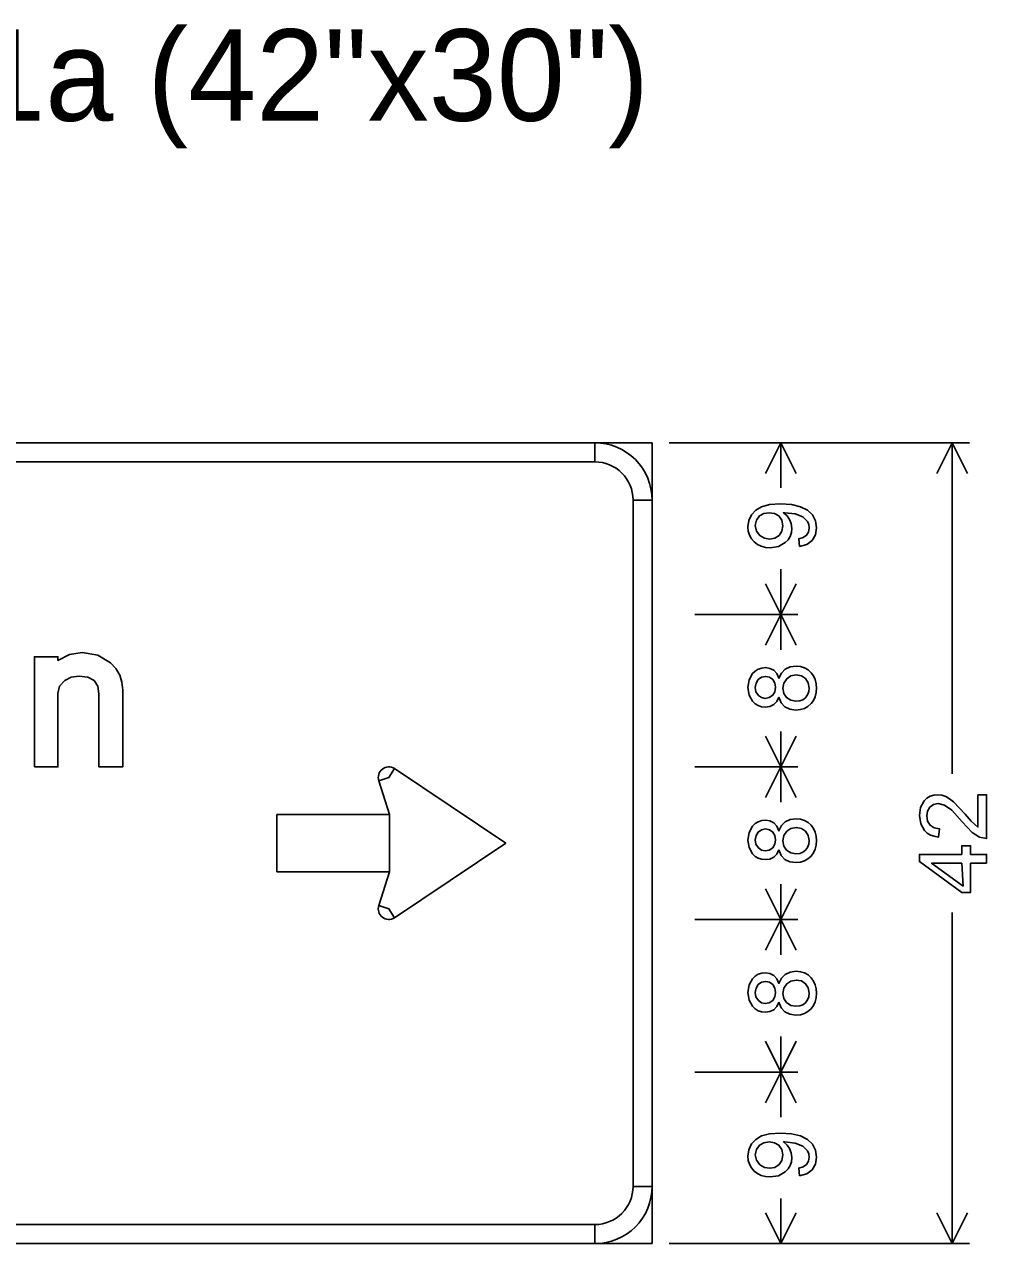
# Model space of a CAD drawing. Extents: x 620864 to 620948.6, y 415499.7 to 415559.1.
# Drawn here: x 620910.82 to 620915.03, y 415523.96 to 415529.29 of the extents above; entities that cross this region are included whole.
import ezdxf

# ---------------------------------------------------------------- set-up
doc = ezdxf.new("R2010")
doc.units = 0
doc.layers.add('SIGNS', color=7, linetype='Continuous')

msp = doc.modelspace()

# ---------------------------------------------------------------- linework, layer by layer
at = {"layer": 'SIGNS'}
for p, q in [((620913.568, 415527.462), (620905.568, 415527.462)), ((620913.318, 415527.462), (620913.318, 415527.3787)), ((620913.568, 415523.962), (620913.568, 415527.462)), ((620914.9555, 415527.462), (620913.643, 415527.462)), ((620914.2055, 415527.462), (620913.7555, 415527.462)), ((620914.0634, 415527.3279), (620914.1305, 415527.462)), ((620914.1305, 415527.265), (620914.1305, 415527.462)), ((620914.1976, 415527.3279), (620914.1305, 415527.462)), ((620914.8134, 415527.3279), (620914.8805, 415527.462)), ((620914.8805, 415526.0148), (620914.8805, 415527.462)), ((620914.9476, 415527.3279), (620914.8805, 415527.462)), ((620913.4846, 415527.212), (620913.568, 415527.212)), ((620914.1305, 415526.9091), (620914.1305, 415526.712)), ((620914.0634, 415526.8462), (620914.1305, 415526.712)), ((620914.1976, 415526.8462), (620914.1305, 415526.712)), ((620914.2055, 415526.712), (620913.7555, 415526.712)), ((620914.0634, 415526.5779), (620914.1305, 415526.712)), ((620914.1305, 415526.5574), (620914.1305, 415526.712)), ((620914.1976, 415526.5779), (620914.1305, 415526.712)), ((620914.1305, 415526.2), (620914.1305, 415526.0454)), ((620914.0634, 415526.1795), (620914.1305, 415526.0454)), ((620914.1976, 415526.1795), (620914.1305, 415526.0454)), ((620912.4176, 415525.9985), (620912.4422, 415526.0384)), ((620914.2055, 415526.0454), (620913.7555, 415526.0454)), ((620914.0634, 415525.9112), (620914.1305, 415526.0454)), ((620914.1305, 415525.8907), (620914.1305, 415526.0454)), ((620914.1976, 415525.9112), (620914.1305, 415526.0454)), ((620912.3729, 415525.9844), (620912.4176, 415525.9985)), ((620914.0634, 415525.5129), (620914.1305, 415525.3787)), ((620914.1305, 415525.5334), (620914.1305, 415525.3787)), ((620914.1976, 415525.5129), (620914.1305, 415525.3787)), ((620912.4176, 415525.4255), (620912.3729, 415525.4397)), ((620912.4422, 415525.3857), (620912.4176, 415525.4255)), ((620914.8805, 415525.4093), (620914.8805, 415523.962)), ((620914.2055, 415525.3787), (620913.7555, 415525.3787)), ((620914.0634, 415525.2445), (620914.1305, 415525.3787)), ((620914.1305, 415525.224), (620914.1305, 415525.3787)), ((620914.1976, 415525.2445), (620914.1305, 415525.3787)), ((620914.1305, 415524.8667), (620914.1305, 415524.712)), ((620914.0634, 415524.8462), (620914.1305, 415524.712)), ((620914.1976, 415524.8462), (620914.1305, 415524.712)), ((620914.2055, 415524.712), (620913.7555, 415524.712)), ((620914.2055, 415524.712), (620913.7555, 415524.712)), ((620914.0634, 415524.5779), (620914.1305, 415524.712)), ((620914.1305, 415524.515), (620914.1305, 415524.712)), ((620914.1976, 415524.5779), (620914.1305, 415524.712)), ((620913.568, 415524.212), (620913.4846, 415524.212)), ((620914.1305, 415524.1591), (620914.1305, 415523.962)), ((620914.0634, 415524.0962), (620914.1305, 415523.962)), ((620914.1976, 415524.0962), (620914.1305, 415523.962)), ((620914.8134, 415524.0962), (620914.8805, 415523.962)), ((620914.9476, 415524.0962), (620914.8805, 415523.962)), ((620913.318, 415524.0454), (620913.318, 415523.962)), ((620905.568, 415523.962), (620913.568, 415523.962)), ((620914.9555, 415523.962), (620913.643, 415523.962)), ((620914.2055, 415523.962), (620913.7555, 415523.962))]:
    msp.add_line(p, q, dxfattribs=at)
for points in [[(620913.318, 415527.3787), (620905.818, 415527.3787), (620905.818, 415527.462), (620913.318, 415527.462), (620913.318, 415527.3787), (620913.318, 415527.3787)], [(620913.4846, 415524.212), (620913.4846, 415527.212), (620913.568, 415527.212), (620913.568, 415524.212), (620913.4846, 415524.212), (620913.4846, 415524.212)], [(620910.868, 415526.0454), (620910.9705, 415526.0454), (620910.9705, 415526.3657), (620910.9777, 415526.3985), (620911, 415526.4237), (620911.0284, 415526.4375), (620911.0639, 415526.4422), (620911.1013, 415526.4371), (620911.1284, 415526.4227), (620911.1446, 415526.3987), (620911.15, 415526.365), (620911.15, 415526.0454), (620911.2536, 415526.0454), (620911.2536, 415526.3807), (620911.2501, 415526.4155), (620911.2404, 415526.4471), (620911.2237, 415526.4754), (620911.2009, 415526.5007), (620911.1443, 415526.5341), (620911.0769, 415526.5454), (620911.0212, 415526.5367), (620910.9707, 415526.5109), (620910.9707, 415526.5267), (620910.868, 415526.5267)], [(620912.928, 415525.712), (620912.4422, 415526.0384), (620912.4176, 415525.9985), (620912.3729, 415525.9844), (620912.4194, 415525.837), (620912.4194, 415525.587), (620912.3729, 415525.4397), (620912.4176, 415525.4255), (620912.4422, 415525.3857), (620912.928, 415525.712), (620912.928, 415525.712)], [(620914.9922, 415525.9237), (620914.9922, 415525.7823), (620914.9625, 415525.8082), (620914.9368, 415525.8383), (620914.8861, 415525.893), (620914.8688, 415525.9063), (620914.8515, 415525.916), (620914.8342, 415525.9217), (620914.8169, 415525.9237), (620914.7992, 415525.922), (620914.7835, 415525.9169), (620914.7696, 415525.9084), (620914.7575, 415525.8968), (620914.7421, 415525.8682), (620914.7369, 415525.8332), (620914.7423, 415525.7961), (620914.7583, 415525.7673), (620914.7703, 415525.7562), (620914.7845, 415525.7478), (620914.8012, 415525.7421), (620914.8202, 415525.739), (620914.8239, 415525.7752), (620914.8012, 415525.779), (620914.7837, 415525.7902), (620914.7725, 415525.8079), (620914.7688, 415525.8313), (620914.7724, 415525.8522), (620914.7824, 415525.8693), (620914.7987, 415525.8813), (620914.8191, 415525.8854), (620914.847, 415525.8779), (620914.8778, 415525.8558), (620914.9233, 415525.8057), (620914.9672, 415525.7594), (620914.9996, 415525.7386), (620915.0305, 415525.7322), (620915.0305, 415525.9237)], [(620911.928, 415525.587), (620911.928, 415525.837), (620912.4194, 415525.837), (620912.4194, 415525.587), (620911.928, 415525.587), (620911.928, 415525.587)], [(620905.818, 415524.0454), (620913.318, 415524.0454), (620913.318, 415523.962), (620905.818, 415523.962), (620905.818, 415524.0454), (620905.818, 415524.0454)]]:
    msp.add_lwpolyline(points, close=True, dxfattribs=at)
for points in [[(620914.2125, 415527.0087), (620914.244, 415527.0176), (620914.2674, 415527.0347), (620914.2821, 415527.0592), (620914.2869, 415527.0905), (620914.2826, 415527.1205), (620914.2694, 415527.1465), (620914.2476, 415527.1675), (620914.2169, 415527.1827), (620914.1774, 415527.1917), (620914.129, 415527.1947), (620914.0814, 415527.1917), (620914.0464, 415527.1825), (620914.0217, 415527.1678), (620914.0027, 415527.1475), (620913.9908, 415527.1226), (620913.9869, 415527.0948), (620913.9887, 415527.0759), (620913.9937, 415527.0586), (620914.002, 415527.043), (620914.0136, 415527.0293), (620914.0281, 415527.0178), (620914.0445, 415527.0097), (620914.0633, 415527.0048), (620914.0841, 415527.0032), (620914.1203, 415527.0088), (620914.1503, 415527.0257), (620914.1627, 415527.0385), (620914.1715, 415527.0531), (620914.1768, 415527.0696), (620914.1784, 415527.0879), (620914.1761, 415527.1089), (620914.1692, 415527.1273), (620914.1578, 415527.143), (620914.1419, 415527.1562), (620914.149, 415527.1565), (620914.1929, 415527.1511), (620914.2266, 415527.1379), (620914.2474, 415527.118), (620914.2532, 415527.1047), (620914.255, 415527.0898), (620914.252, 415527.0719), (620914.2434, 415527.0581), (620914.2291, 415527.0482), (620914.2092, 415527.0425), (620914.2125, 415527.0087)], [(620914.08, 415527.1565), (620914.1035, 415527.1528), (620914.1222, 415527.1424), (620914.1357, 415527.124), (620914.1401, 415527.0997), (620914.1359, 415527.0759), (620914.1233, 415527.0572), (620914.1052, 415527.0454), (620914.0828, 415527.0415), (620914.0591, 415527.0454), (620914.0389, 415527.057), (620914.0238, 415527.0763), (620914.0188, 415527.1007), (620914.0238, 415527.1241), (620914.038, 415527.1424), (620914.0572, 415527.1528), (620914.08, 415527.1565)], [(620914.1225, 415526.3502), (620914.1329, 415526.3256), (620914.1488, 415526.308), (620914.1701, 415526.2976), (620914.1969, 415526.2942), (620914.2165, 415526.2959), (620914.2339, 415526.3013), (620914.2495, 415526.3099), (620914.2628, 415526.3221), (620914.2734, 415526.3363), (620914.2808, 415526.3523), (620914.2854, 415526.3702), (620914.2869, 415526.3899), (620914.2855, 415526.4091), (620914.281, 415526.4269), (620914.2735, 415526.4429), (620914.263, 415526.4573), (620914.2498, 415526.4697), (620914.2344, 415526.4787), (620914.2172, 415526.4839), (620914.1979, 415526.4856), (620914.1717, 415526.4822), (620914.1503, 415526.4723), (620914.134, 415526.4558), (620914.1225, 415526.4328), (620914.1128, 415526.4531), (620914.0996, 415526.4676), (620914.0832, 415526.4763), (620914.0637, 415526.4793), (620914.0471, 415526.4776), (620914.0322, 415526.4727), (620914.0189, 415526.4645), (620914.0071, 415526.4532), (620913.992, 415526.4258), (620913.9869, 415526.3926), (620913.9919, 415526.3595), (620914.0067, 415526.3326), (620914.0182, 415526.3213), (620914.0313, 415526.3133), (620914.0461, 415526.3085), (620914.0627, 415526.3069), (620914.0829, 415526.3096), (620914.0996, 415526.3177), (620914.1128, 415526.3312), (620914.1225, 415526.3502)], [(620914.1969, 415526.3325), (620914.1744, 415526.3366), (620914.156, 415526.3485), (620914.144, 415526.3665), (620914.1401, 415526.389), (620914.1444, 415526.412), (620914.1566, 415526.4308), (620914.1752, 415526.4432), (620914.1981, 415526.4474), (620914.2209, 415526.4433), (620914.239, 415526.4312), (620914.251, 415526.4128), (620914.255, 415526.3902), (620914.2531, 415526.3746), (620914.2474, 415526.3604), (620914.2385, 415526.348), (620914.2271, 415526.3393), (620914.2133, 415526.3341), (620914.1969, 415526.3325)], [(620914.0623, 415526.3452), (620914.0462, 415526.3484), (620914.0326, 415526.3579), (620914.0222, 415526.3738), (620914.0188, 415526.3931), (620914.0223, 415526.4119), (620914.0323, 415526.4273), (620914.0469, 415526.4376), (620914.0643, 415526.441), (620914.082, 415526.4374), (620914.096, 415526.4272), (620914.1052, 415526.412), (620914.1081, 415526.3935), (620914.105, 415526.3738), (620914.0952, 415526.3584), (620914.0805, 415526.3484), (620914.0623, 415526.3452)], [(620914.1225, 415525.6836), (620914.1329, 415525.6589), (620914.1488, 415525.6414), (620914.1701, 415525.6309), (620914.1969, 415525.6275), (620914.2165, 415525.6293), (620914.2339, 415525.6346), (620914.2495, 415525.6433), (620914.2628, 415525.6554), (620914.2734, 415525.6696), (620914.2808, 415525.6856), (620914.2854, 415525.7035), (620914.2869, 415525.7233), (620914.2855, 415525.7425), (620914.281, 415525.7602), (620914.2735, 415525.7762), (620914.263, 415525.7907), (620914.2498, 415525.803), (620914.2344, 415525.812), (620914.2172, 415525.8172), (620914.1979, 415525.819), (620914.1717, 415525.8155), (620914.1503, 415525.8056), (620914.134, 415525.7892), (620914.1225, 415525.7661), (620914.1128, 415525.7864), (620914.0996, 415525.8009), (620914.0832, 415525.8096), (620914.0637, 415525.8126), (620914.0471, 415525.8109), (620914.0322, 415525.806), (620914.0189, 415525.7978), (620914.0071, 415525.7866), (620913.992, 415525.7591), (620913.9869, 415525.7259), (620913.9919, 415525.6928), (620914.0067, 415525.6659), (620914.0182, 415525.6546), (620914.0313, 415525.6466), (620914.0461, 415525.6419), (620914.0627, 415525.6403), (620914.0829, 415525.643), (620914.0996, 415525.651), (620914.1128, 415525.6645), (620914.1225, 415525.6836)], [(620914.0623, 415525.6786), (620914.0462, 415525.6818), (620914.0326, 415525.6912), (620914.0222, 415525.7072), (620914.0188, 415525.7264), (620914.0223, 415525.7452), (620914.0323, 415525.7606), (620914.0469, 415525.7709), (620914.0643, 415525.7743), (620914.082, 415525.7707), (620914.096, 415525.7605), (620914.1052, 415525.7453), (620914.1081, 415525.7268), (620914.105, 415525.7072), (620914.0952, 415525.6917), (620914.0805, 415525.6818), (620914.0623, 415525.6786)], [(620914.1969, 415525.6658), (620914.1744, 415525.6699), (620914.156, 415525.6819), (620914.144, 415525.6998), (620914.1401, 415525.7223), (620914.1444, 415525.7454), (620914.1566, 415525.7641), (620914.1752, 415525.7765), (620914.1981, 415525.7807), (620914.2209, 415525.7766), (620914.239, 415525.7645), (620914.251, 415525.7462), (620914.255, 415525.7235), (620914.2531, 415525.708), (620914.2474, 415525.6937), (620914.2385, 415525.6814), (620914.2271, 415525.6727), (620914.2133, 415525.6674), (620914.1969, 415525.6658)], [(620915.0305, 415525.6247), (620915.0305, 415525.663), (620914.9603, 415525.663), (620914.9603, 415525.7008), (620914.922, 415525.7008), (620914.922, 415525.663), (620914.7369, 415525.663), (620914.7369, 415525.6315), (620914.922, 415525.497), (620914.9603, 415525.497), (620914.9603, 415525.6247), (620915.0305, 415525.6247)], [(620914.922, 415525.6247), (620914.9273, 415525.5246), (620914.7895, 415525.6247), (620914.922, 415525.6247)], [(620914.1225, 415525.0169), (620914.1329, 415524.9922), (620914.1488, 415524.9747), (620914.1701, 415524.9642), (620914.1969, 415524.9608), (620914.2165, 415524.9626), (620914.2339, 415524.9679), (620914.2495, 415524.9766), (620914.2628, 415524.9888), (620914.2734, 415525.0029), (620914.2808, 415525.019), (620914.2854, 415525.0368), (620914.2869, 415525.0566), (620914.2855, 415525.0758), (620914.281, 415525.0936), (620914.2735, 415525.1095), (620914.263, 415525.124), (620914.2498, 415525.1364), (620914.2344, 415525.1454), (620914.2172, 415525.1505), (620914.1979, 415525.1523), (620914.1717, 415525.1488), (620914.1503, 415525.1389), (620914.134, 415525.1225), (620914.1225, 415525.0995), (620914.1128, 415525.1197), (620914.0996, 415525.1343), (620914.0832, 415525.1429), (620914.0637, 415525.1459), (620914.0471, 415525.1443), (620914.0322, 415525.1393), (620914.0189, 415525.1312), (620914.0071, 415525.1199), (620913.992, 415525.0925), (620913.9869, 415525.0593), (620913.9919, 415525.0262), (620914.0067, 415524.9992), (620914.0182, 415524.988), (620914.0313, 415524.98), (620914.0461, 415524.9752), (620914.0627, 415524.9736), (620914.0829, 415524.9763), (620914.0996, 415524.9844), (620914.1128, 415524.9978), (620914.1225, 415525.0169)], [(620914.1969, 415524.9991), (620914.1744, 415525.0032), (620914.156, 415525.0152), (620914.144, 415525.0331), (620914.1401, 415525.0557), (620914.1444, 415525.0787), (620914.1566, 415525.0975), (620914.1752, 415525.1098), (620914.1981, 415525.114), (620914.2209, 415525.1099), (620914.239, 415525.0979), (620914.251, 415525.0795), (620914.255, 415525.0569), (620914.2531, 415525.0413), (620914.2474, 415525.0271), (620914.2385, 415525.0147), (620914.2271, 415525.006), (620914.2133, 415525.0007), (620914.1969, 415524.9991)], [(620914.0623, 415525.0119), (620914.0462, 415525.0151), (620914.0326, 415525.0246), (620914.0222, 415525.0405), (620914.0188, 415525.0598), (620914.0223, 415525.0785), (620914.0323, 415525.094), (620914.0469, 415525.1043), (620914.0643, 415525.1076), (620914.082, 415525.104), (620914.096, 415525.0939), (620914.1052, 415525.0786), (620914.1081, 415525.0602), (620914.105, 415525.0405), (620914.0952, 415525.0251), (620914.0805, 415525.0151), (620914.0623, 415525.0119)], [(620914.2125, 415524.2587), (620914.244, 415524.2676), (620914.2674, 415524.2847), (620914.2821, 415524.3092), (620914.2869, 415524.3405), (620914.2826, 415524.3705), (620914.2694, 415524.3965), (620914.2476, 415524.4175), (620914.2169, 415524.4327), (620914.1774, 415524.4417), (620914.129, 415524.4447), (620914.0814, 415524.4417), (620914.0464, 415524.4325), (620914.0217, 415524.4178), (620914.0027, 415524.3975), (620913.9908, 415524.3726), (620913.9869, 415524.3448), (620913.9887, 415524.3259), (620913.9937, 415524.3086), (620914.002, 415524.293), (620914.0136, 415524.2793), (620914.0281, 415524.2678), (620914.0445, 415524.2597), (620914.0633, 415524.2548), (620914.0841, 415524.2532), (620914.1203, 415524.2588), (620914.1503, 415524.2757), (620914.1627, 415524.2885), (620914.1715, 415524.3031), (620914.1768, 415524.3196), (620914.1784, 415524.3379), (620914.1761, 415524.3589), (620914.1692, 415524.3773), (620914.1578, 415524.393), (620914.1419, 415524.4062), (620914.149, 415524.4065), (620914.1929, 415524.4012), (620914.2266, 415524.3879), (620914.2474, 415524.368), (620914.2532, 415524.3547), (620914.255, 415524.3398), (620914.252, 415524.3219), (620914.2434, 415524.3081), (620914.2291, 415524.2982), (620914.2092, 415524.2925), (620914.2125, 415524.2587)], [(620914.08, 415524.4065), (620914.1035, 415524.4028), (620914.1222, 415524.3924), (620914.1357, 415524.374), (620914.1401, 415524.3497), (620914.1359, 415524.3259), (620914.1233, 415524.3072), (620914.1052, 415524.2954), (620914.0828, 415524.2915), (620914.0591, 415524.2954), (620914.0389, 415524.307), (620914.0238, 415524.3263), (620914.0188, 415524.3507), (620914.0238, 415524.3741), (620914.038, 415524.3924), (620914.0572, 415524.4028), (620914.08, 415524.4065)]]:
    msp.add_lwpolyline(points, dxfattribs=at)
for centre, radius, start, end in [((620913.318, 415527.212), 0.25, 0, 90.0002), ((620913.318, 415527.212), 0.1667, 0, 90.0002), ((620912.4176, 415525.9985), 0.0469, 58.2847, 197.5209), ((620912.4176, 415525.4255), 0.0469, 162.4794, 301.715), ((620913.318, 415524.212), 0.25, 270.0001, 0.0003), ((620913.318, 415524.212), 0.1667, 270.0001, 0.0003)]:
    msp.add_arc(centre, radius, start, end, dxfattribs=at)

# ---------------------------------------------------------------- texts
msp.add_text('R5-1a (42"x30")', height=0.4, rotation=0, dxfattribs=at).set_placement((620909.7558, 415528.8694))

doc.saveas('drawing.dxf')
